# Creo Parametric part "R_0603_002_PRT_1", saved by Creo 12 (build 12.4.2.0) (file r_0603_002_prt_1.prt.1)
Units: Custom; MM, KILOGRAM, SECS

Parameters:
  PTC_WM_ITERATION = "0"
  PTC_WM_VERSION = "-.0"
  PTC_WM_LIFECYCLE_STATE = "In Work"
  PTC_WM_LIFECYCLE = "MO_CADDocument"
  PTC_WM_CREATED_BY = "Maximilian Roepper (Z0017RMS: MO)"
  PTC_WM_CREATED_ON = "18-Sep-26 11:36:42 AM"
  PTC_WM_MODIFIED_BY = "Maximilian Roepper (Z0017RMS: MO)"
  PTC_WM_MODIFIED_ON = "18-Sep-26 11:36:46 AM"
  PDMLINKNUMBER = "PDM000071454757"
  PTC_WM_NAME = "r_0603_002_prt_1.prt"
  PTC_WM_NUMBER = "PDM000071454757"

Other parameters: WEIGHT, WEIGHT_FACTOR, WEIGHT_ADD, _MASS_TEMP, _DIFF_TEMP, MC_ERRORS, SUPPLIER

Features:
  1. coordinate system
  2. datum plane "PRT_YZ"
  3. datum plane "PRT_XY"
  4. datum plane "PRT_XZ"
  5. coordinate system
  6. datum axis
  7. datum axis
  8. datum axis
  9. coordinate system
  10. imported feature
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
Other named items: PRT, SIEMENS_MO, DRW_VIEW_ORG, PRT_X, PRT_Y, PRT_Z, CS0, ROUGH_GROB

Layers: 00_STD_CSYS-KSYS, 01_STD_PLANES-EBENEN, 02_STD_AXES-ACHSEN, 03_STD_CSYS-KSYS, 24_IMPORT_FEAT-IMPORT_KE

Surfaces: 18 plane, 8 cylinder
